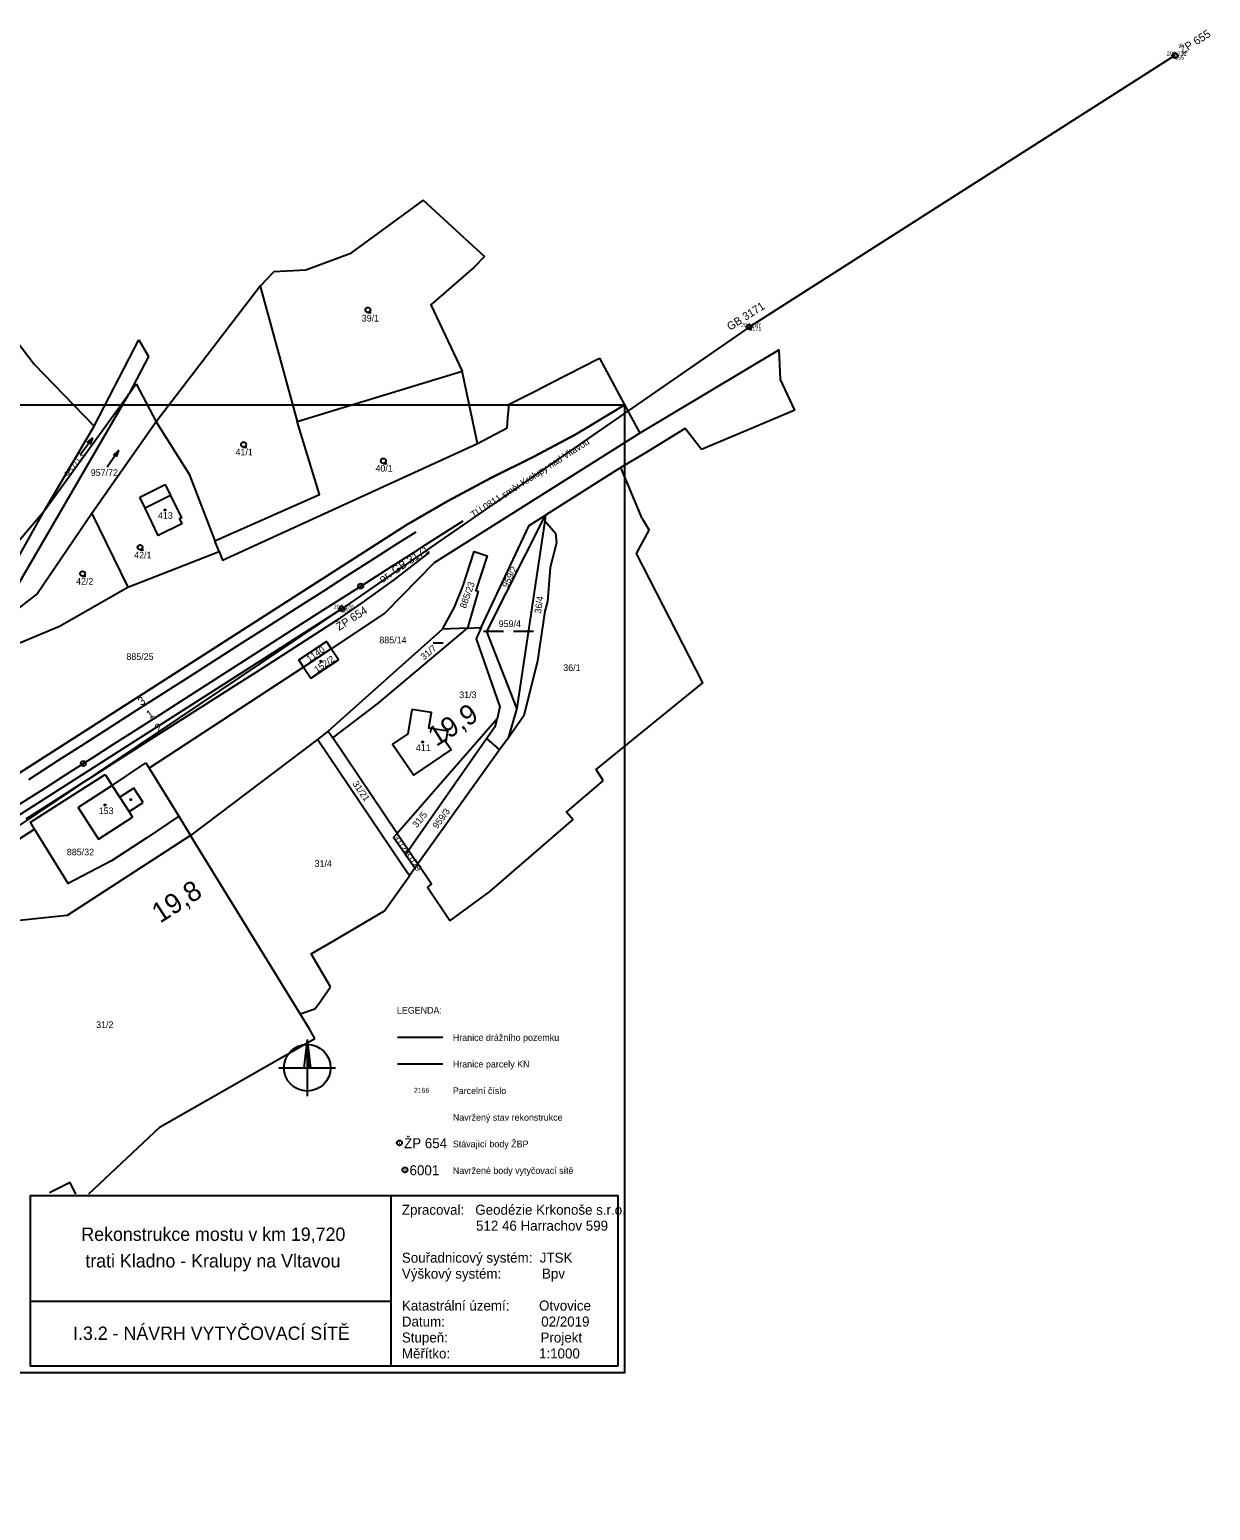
# Model space of a CAD drawing. Extents: x -752210 to -751291, y -1028374 to -1027785.
# Drawn here: x -751645.7 to -751290.6, y -1028230 to -1027784.8 of the extents above; entities that cross this region are included whole.
import ezdxf

# ---------------------------------------------------------------- set-up
doc = ezdxf.new("R2010")
doc.units = 0
for name, color, linetype in [('02_Osa_koleje', 7, 'Continuous'), ('03_Staničení', 7, 'Continuous'), ('Legenda', 7, 'Continuous'), ('Legenda 1', 7, 'Continuous'), ('Legenda 2', 7, 'Continuous'), ('Vrstva 4', 7, 'Continuous'), ('Vrstva 53', 7, 'Continuous'), ('Vrstva 55', 7, 'Continuous'), ('Vrstva 56', 7, 'Continuous'), ('Vrstva 57', 7, 'Continuous'), ('Vrstva 58', 7, 'Continuous'), ('Vrstva 59', 7, 'Continuous'), ('Vrstva 60', 7, 'Continuous'), ('Vrstva 61', 7, 'Continuous'), ('Vrstva 63', 7, 'Continuous')]:
    doc.layers.add(name, color=color, linetype=linetype)

msp = doc.modelspace()

# ---------------------------------------------------------------- linework, layer by layer
at = {"layer": '02_Osa_koleje'}
for p, q in [((-751535.5, -1027939.59), (-751529.38, -1027935.82)), ((-751541.77, -1027943.62), (-751535.5, -1027939.59)), ((-751536.85, -1027946.23), (-751529.25, -1027941.37)), ((-751527.97, -1027944.03), (-751525.45, -1027941.98)), ((-751550.25, -1027949.06), (-751541.77, -1027943.62)), ((-751544.45, -1027951.09), (-751536.85, -1027946.23)), ((-751536.02, -1027950.26), (-751527.97, -1027944.03)), ((-751557.18, -1027953.5), (-751550.25, -1027949.06)), ((-751551.57, -1027955.64), (-751544.45, -1027951.09)), ((-751545.62, -1027957.19), (-751536.02, -1027950.26)), ((-751565.35, -1027958.72), (-751557.18, -1027953.5)), ((-751557.44, -1027959.4), (-751551.57, -1027955.64)), ((-751573.24, -1027963.75), (-751565.35, -1027958.72)), ((-751565.26, -1027964.39), (-751557.44, -1027959.4)), ((-751552.14, -1027961.63), (-751545.62, -1027957.19)), ((-751581.95, -1027969.31), (-751573.24, -1027963.75)), ((-751569.81, -1027967.31), (-751565.26, -1027964.39)), ((-751560.92, -1027967.3), (-751552.14, -1027961.63)), ((-751588.99, -1027973.81), (-751581.95, -1027969.31)), ((-751576.84, -1027971.8), (-751569.81, -1027967.31)), ((-751569.42, -1027972.75), (-751560.92, -1027967.3)), ((-751584.69, -1027976.81), (-751576.84, -1027971.8)), ((-751577.55, -1027977.95), (-751569.42, -1027972.75)), ((-751597.35, -1027979.15), (-751588.99, -1027973.81)), ((-751592.46, -1027981.78), (-751584.69, -1027976.81)), ((-751585.46, -1027983), (-751577.55, -1027977.95)), ((-751605.88, -1027984.61), (-751597.35, -1027979.15)), ((-751599.97, -1027986.58), (-751592.46, -1027981.78)), ((-751614.37, -1027990.06), (-751605.88, -1027984.61)), ((-751606.23, -1027990.59), (-751599.97, -1027986.58)), ((-751593.8, -1027988.33), (-751585.46, -1027983)), ((-751622.32, -1027995.15), (-751614.37, -1027990.06)), ((-751613.64, -1027995.33), (-751606.23, -1027990.59)), ((-751601.83, -1027993.46), (-751593.8, -1027988.33)), ((-751630.17, -1028000.17), (-751622.32, -1027995.15)), ((-751621.23, -1028000.17), (-751613.64, -1027995.33)), ((-751608.88, -1027997.98), (-751601.83, -1027993.46)), ((-751636.92, -1028004.49), (-751630.17, -1028000.17)), ((-751626.18, -1028003.34), (-751621.23, -1028000.17)), ((-751616.69, -1028002.97), (-751608.88, -1027997.98)), ((-751645.91, -1028010.23), (-751636.92, -1028004.49)), ((-751633.49, -1028008.01), (-751626.18, -1028003.34)), ((-751624.19, -1028007.75), (-751616.69, -1028002.97)), ((-751640.92, -1028012.76), (-751633.49, -1028008.01)), ((-751630.51, -1028011.79), (-751624.19, -1028007.75)), ((-751648.69, -1028017.73), (-751640.92, -1028012.76)), ((-751638.2, -1028016.71), (-751630.51, -1028011.79)), ((-751646.64, -1028022.11), (-751638.2, -1028016.71))]:
    msp.add_line(p, q, dxfattribs=at)
msp.add_lwpolyline([(-751529.25, -1027941.37), (-751526.83, -1027939.82), (-751515.32, -1027932.45)], dxfattribs=at)
at = {"layer": '03_Staničení'}
for centre in [(-751546.08, -1027952.12), (-751629.49, -1028005.46)]:
    msp.add_circle(centre, 0.75, dxfattribs=at)
at = {"layer": 'Legenda 1'}
for p, q in [((-751562.16, -1028088.42), (-751563.17, -1028096.92)), ((-751562.16, -1028088.42), (-751562.16, -1028105.42)), ((-751562.16, -1028088.42), (-751561.16, -1028096.92)), ((-751562.16, -1028090.54), (-751561.41, -1028096.92)), ((-751562.16, -1028092.67), (-751561.66, -1028096.92)), ((-751570.66, -1028096.92), (-751553.66, -1028096.92)), ((-751562.16, -1028094.79), (-751561.91, -1028096.92)), ((-751562.16, -1028096.92), (-751562.16, -1028096.92)), ((-751536.92, -1028186.6), (-751536.92, -1028135.35)), ((-751536.92, -1028167.2), (-751645.4, -1028167.2))]:
    msp.add_line(p, q, dxfattribs=at)
msp.add_lwpolyline([(-751468.79, -1028186.6), (-751645.4, -1028186.6), (-751645.4, -1028135.35), (-751468.79, -1028135.35)], close=True, dxfattribs=at)
msp.add_circle((-751562.16, -1028096.92), 7, dxfattribs=at)
at = {"layer": 'Vrstva 4'}
msp.add_lwpolyline([(-751880.79, -1027897.6), (-751466.79, -1027897.6), (-751466.79, -1028188.6), (-751880.79, -1028188.6)], close=True, dxfattribs=at)
at = {"layer": 'Vrstva 53'}
msp.add_line((-751535.06, -1028087.71), (-751521.36, -1028087.71), dxfattribs=at)
for points in [[(-751890.97, -1028163.13), (-751806.75, -1028109.29), (-751808.53, -1028106.05), (-751798.29, -1028099.68), (-751750.57, -1028069.21), (-751709.61, -1028036.63), (-751702.85, -1028029.39), (-751690.7, -1028035.11), (-751634.83, -1027999.42), (-751532.07, -1027933.64), (-751519.82, -1027926.47), (-751506.87, -1027919.58), (-751494.13, -1027913.25), (-751481.54, -1027906.54), (-751469.19, -1027899.14), (-751466.79, -1027897.6)], [(-751462.19, -1027906.18), (-751523.97, -1027945.11), (-751538.82, -1027960.28), (-751554.98, -1027970.94), (-751563.33, -1027976.45), (-751609.72, -1028006.9), (-751600.73, -1028021.25), (-751610.42, -1028027.79), (-751621, -1028034.71), (-751634.07, -1028041.54), (-751644.14, -1028025.2), (-751657.66, -1028033.82)]]:
    msp.add_lwpolyline(points, dxfattribs=at)
at = {"layer": 'Vrstva 55'}
for p, q in [((-751514.9, -1027847.48), (-751527.35, -1027836.07)), ((-751514.9, -1027847.48), (-751508.89, -1027852.99)), ((-751670.74, -1027850.8), (-751644.31, -1027885.35)), ((-751572.26, -1027857.64), (-751576.37, -1027861.95)), ((-751576.37, -1027861.95), (-751607.59, -1027902.71)), ((-751576.37, -1027861.95), (-751565.18, -1027902.61)), ((-751626.22, -1027904.08), (-751612.77, -1027878.04)), ((-751612.77, -1027878.04), (-751609.94, -1027883.14)), ((-751609.94, -1027883.14), (-751615.69, -1027894.18)), ((-751489.04, -1027891.13), (-751474.31, -1027883.58)), ((-751474.31, -1027883.58), (-751466.79, -1027897.6)), ((-751420.23, -1027881.1), (-751462.19, -1027906.18)), ((-751419.83, -1027889.96), (-751420.23, -1027881.1)), ((-751626.22, -1027904.08), (-751644.31, -1027885.35)), ((-751565.18, -1027902.61), (-751515.53, -1027887.47)), ((-751511.01, -1027909.22), (-751515.53, -1027887.47)), ((-751615.69, -1027894.18), (-751613.65, -1027891.36)), ((-751613.65, -1027891.36), (-751607.59, -1027902.71)), ((-751493.66, -1027893.5), (-751489.04, -1027891.13)), ((-751415.54, -1027899.18), (-751419.83, -1027889.96)), ((-751656.71, -1027964.65), (-751615.69, -1027894.18)), ((-751641.14, -1027929.37), (-751615.69, -1027894.18)), ((-751466.79, -1027897.6), (-751469.19, -1027899.14)), ((-751466.79, -1027897.6), (-751462.19, -1027906.18)), ((-751641.14, -1027929.37), (-751626.22, -1027904.08)), ((-751607.59, -1027902.71), (-751626.99, -1027930.26)), ((-751460.76, -1027912.3), (-751467.89, -1027916.43)), ((-751467.89, -1027916.43), (-751490.52, -1027930.81)), ((-751461.44, -1027931.84), (-751467.89, -1027916.43)), ((-751612.52, -1027925.39), (-751604.88, -1027921.62)), ((-751626.99, -1027930.26), (-751616.15, -1027952.42)), ((-751490.76, -1027932.54), (-751499.13, -1027988.78)), ((-751490.52, -1027930.81), (-751490.76, -1027932.54)), ((-751461.44, -1027931.84), (-751459.38, -1027935.34)), ((-751616.15, -1027952.42), (-751588.69, -1027941.76)), ((-751588.69, -1027941.76), (-751589.95, -1027938.49)), ((-751510.79, -1027953.68), (-751513.96, -1027964.72)), ((-751521.54, -1027965.05), (-751517.93, -1027958.42)), ((-751513.96, -1027964.72), (-751521.54, -1027965.05)), ((-751513.96, -1027964.72), (-751509.88, -1027964.53)), ((-751521.54, -1027965.05), (-751555.86, -1027995.74)), ((-751554.98, -1027970.94), (-751563.33, -1027976.45)), ((-751563.33, -1027976.45), (-751609.72, -1028006.9)), ((-751499.13, -1027988.78), (-751501.78, -1027997.8)), ((-751555.86, -1027995.74), (-751559.11, -1027998.2)), ((-751555.86, -1027995.74), (-751554.45, -1027997.78)), ((-751505.06, -1027992), (-751535.11, -1028026.46)), ((-751559.11, -1027998.2), (-751597.31, -1028027.06)), ((-751535.11, -1028026.46), (-751554.45, -1027997.78)), ((-751531.7, -1028031.5), (-751508.24, -1027997.97)), ((-751508.24, -1027997.97), (-751504.35, -1028001.39)), ((-751501.78, -1027997.8), (-751504.35, -1028001.39)), ((-751504.35, -1028001.39), (-751528.9, -1028035.64)), ((-751610.74, -1028005.23), (-751609.72, -1028006.9)), ((-751609.72, -1028006.9), (-751600.73, -1028021.25)), ((-751600.73, -1028021.25), (-751597.31, -1028027.06)), ((-751564.25, -1028080.75), (-751597.31, -1028027.06)), ((-751535.11, -1028026.46), (-751531.7, -1028031.5)), ((-751531.7, -1028031.5), (-751532.76, -1028032.72)), ((-751531.7, -1028031.5), (-751528.9, -1028035.64)), ((-751529.84, -1028036.97), (-751532.76, -1028032.72)), ((-751528.9, -1028035.64), (-751529.84, -1028036.97)), ((-751538.93, -1028049.78), (-751531.43, -1028039.2)), ((-751529.84, -1028036.97), (-751531.43, -1028039.2)), ((-751519.27, -1028052.78), (-751525.97, -1028042.75)), ((-751558.81, -1028077.79), (-751555.13, -1028072.6)), ((-751561.61, -1028085.17), (-751564.25, -1028080.75)), ((-751577.95, -1028098.41), (-751559.85, -1028088.11)), ((-751559.85, -1028088.11), (-751561.61, -1028085.17)), ((-751535.06, -1028095.71), (-751521.36, -1028095.71))]:
    msp.add_line(p, q, dxfattribs=at)
for points in [[(-751527.35, -1027836.07), (-751549.35, -1027852.19), (-751562.57, -1027857.16), (-751572.26, -1027857.64)], [(-751508.89, -1027852.99), (-751512.04, -1027856.33), (-751525.01, -1027867.6), (-751515.53, -1027887.47)], [(-751511.01, -1027909.22), (-751502.05, -1027904.53), (-751501.8, -1027901.52), (-751501.41, -1027897.47), (-751493.66, -1027893.5)], [(-751469.19, -1027899.14), (-751481.54, -1027906.54), (-751494.13, -1027913.25), (-751506.87, -1027919.58), (-751519.82, -1027926.47), (-751532.07, -1027933.64), (-751634.83, -1027999.42), (-751690.7, -1028035.11), (-751702.85, -1028029.39)], [(-751415.54, -1027899.18), (-751429.76, -1027905.22), (-751434.82, -1027907.37), (-751443.56, -1027911.08)], [(-751607.59, -1027902.71), (-751597.69, -1027918.48), (-751589.95, -1027938.49)], [(-751589.95, -1027938.49), (-751558.45, -1027924.61), (-751565.18, -1027902.61)], [(-751462.19, -1027906.18), (-751523.97, -1027945.11), (-751538.82, -1027960.28), (-751554.98, -1027970.94)], [(-751443.56, -1027911.08), (-751448.52, -1027904.72), (-751460.76, -1027912.3)], [(-751588.69, -1027941.76), (-751587.61, -1027944.36), (-751511.01, -1027909.22)], [(-751604.88, -1027921.62), (-751603.25, -1027924.91), (-751599.95, -1027931.6), (-751600.61, -1027931.93), (-751599.87, -1027933.41), (-751606.96, -1027936.93), (-751610.94, -1027928.67), (-751612.52, -1027925.39)], [(-751672, -1027960.17), (-751661.99, -1027953.87), (-751641.14, -1027929.37)], [(-751668.79, -1027968.97), (-751658.03, -1027959.34), (-751641.14, -1027929.37)], [(-751626.99, -1027930.26), (-751643.3, -1027954.3), (-751656.71, -1027964.65)], [(-751509.88, -1027964.53), (-751495.38, -1027933.9), (-751490.52, -1027930.81)], [(-751499.13, -1027988.78), (-751508.14, -1027965.79), (-751490.52, -1027930.81)], [(-751490.76, -1027932.54), (-751487.53, -1027936.17), (-751487.21, -1027939.13), (-751489.07, -1027946.51), (-751489.95, -1027956.74), (-751490.69, -1027959.66), (-751492.95, -1027974.6), (-751497.03, -1027991.17), (-751501.78, -1027997.8)], [(-751473.18, -1028010.52), (-751475.29, -1028007.29), (-751443.25, -1027981.25), (-751463.14, -1027942.28), (-751459.38, -1027935.34)], [(-751517.93, -1027958.42), (-751515.42, -1027952.2), (-751511.94, -1027941.75), (-751508.1, -1027943), (-751511.47, -1027953.46), (-751510.79, -1027953.68)], [(-751651.99, -1027970.58), (-751636.62, -1027964.12), (-751616.15, -1027952.42)], [(-751554.45, -1027997.78), (-751541.05, -1027987.48), (-751513.96, -1027964.72)], [(-751509.88, -1027964.53), (-751511.41, -1027967.96), (-751504.21, -1027988.42), (-751505.06, -1027992)], [(-751563.33, -1027976.45), (-751564.74, -1027974.3), (-751556.39, -1027968.8), (-751554.98, -1027970.94)], [(-751563.33, -1027976.45), (-751561.13, -1027979.79), (-751552.78, -1027974.28), (-751554.98, -1027970.94)], [(-751530.72, -1027989.19), (-751531.91, -1027996.52), (-751536.51, -1027999.67), (-751530.08, -1028008.97), (-751518.89, -1028001.3), (-751520.44, -1027999.07), (-751519.9, -1027995.71), (-751525.59, -1027994.81), (-751524.75, -1027990.16), (-751530.72, -1027989.19)], [(-751508.24, -1027997.97), (-751505.57, -1027994.16), (-751505.06, -1027992)], [(-751531.43, -1028039.2), (-751533.79, -1028035.7), (-751559.11, -1027998.2)], [(-751644.14, -1028025.2), (-751645.38, -1028023.11), (-751622.97, -1028008.73)], [(-751622.97, -1028008.73), (-751620.78, -1028012.09), (-751610.74, -1028005.23)], [(-751611.54, -1028017.13), (-751614.28, -1028012.89), (-751618.5, -1028015.62), (-751620.78, -1028012.09), (-751631.03, -1028018.71), (-751624.93, -1028028.16), (-751614.68, -1028021.54), (-751615.76, -1028019.86), (-751611.54, -1028017.13)], [(-751473.18, -1028010.52), (-751484.17, -1028020.02), (-751482.24, -1028022.26)], [(-751600.73, -1028021.25), (-751610.42, -1028027.79), (-751621, -1028034.71), (-751634.07, -1028041.54), (-751644.14, -1028025.2)], [(-751519.27, -1028052.78), (-751507.37, -1028043.99), (-751482.24, -1028022.26)], [(-751811.98, -1028131.93), (-751700.39, -1028060.59), (-751700.15, -1028061), (-751685.1, -1028051.35), (-751685.36, -1028050.92), (-751657.93, -1028033.4), (-751657.66, -1028033.82), (-751644.14, -1028025.2)], [(-751597.31, -1028027.06), (-751634.36, -1028051.12), (-751685.04, -1028056.42), (-751698.4, -1028064.61)], [(-751532.76, -1028032.72), (-751536.2, -1028027.71), (-751535.11, -1028026.46)], [(-751525.97, -1028042.75), (-751524.75, -1028041.78), (-751528.9, -1028035.64)], [(-751555.13, -1028072.6), (-751560.94, -1028062.65), (-751554.11, -1028058.66), (-751538.93, -1028049.78)], [(-751564.25, -1028080.75), (-751559.85, -1028079.26), (-751558.81, -1028077.79)], [(-751627.84, -1028134.79), (-751606.35, -1028114.7), (-751577.95, -1028098.41)], [(-751631.71, -1028134.9), (-751633.5, -1028131.42), (-751639.67, -1028134.57)]]:
    msp.add_lwpolyline(points, dxfattribs=at)
at = {"layer": 'Vrstva 56'}
for p, q in [((-751603.25, -1027924.91), (-751610.94, -1027928.67)), ((-751615.76, -1028019.86), (-751618.5, -1028015.62))]:
    msp.add_line(p, q, dxfattribs=at)
at = {"layer": 'Vrstva 58'}
for p, q in [((-751543.94, -1027869.85), (-751542.94, -1027869.85)), ((-751630.38, -1027912.48), (-751626.78, -1027907.68)), ((-751622.31, -1027916.3), (-751618.89, -1027911.37)), ((-751581.3, -1027910.33), (-751580.3, -1027910.33)), ((-751539.26, -1027915.25), (-751538.26, -1027915.25)), ((-751612.42, -1027941.21), (-751611.42, -1027941.21)), ((-751629.72, -1027949.14), (-751628.72, -1027949.14)), ((-751524.26, -1027969.13), (-751521.26, -1027969.13)), ((-751509.14, -1027965.72), (-751503.14, -1027965.72)), ((-751500.14, -1027965.72), (-751494.14, -1027965.72))]:
    msp.add_line(p, q, dxfattribs=at)
for points in [[(-751628.38, -1027908.98), (-751626.78, -1027907.68), (-751627.58, -1027909.58)], [(-751620.44, -1027912.73), (-751618.89, -1027911.37), (-751619.62, -1027913.3)]]:
    msp.add_lwpolyline(points, dxfattribs=at)
for centre in [(-751543.94, -1027869.1), (-751581.3, -1027909.58), (-751539.26, -1027914.5), (-751612.42, -1027940.46), (-751629.72, -1027948.39)]:
    msp.add_circle(centre, 0.75, dxfattribs=at)
at = {"layer": 'Vrstva 59'}
for centre in [(-751604.94, -1027929.24), (-751558.09, -1027974.76), (-751527.47, -1027999), (-751622.96, -1028017.93), (-751615.24, -1028016.34)]:
    msp.add_circle(centre, 0.175, dxfattribs=at)
at = {"layer": 'Vrstva 60'}
for p, q in [((-751301.25, -1027792.61), (-751301.25, -1027792.61)), ((-751429.27, -1027874.23), (-751429.27, -1027874.23)), ((-751551.77, -1027958.95), (-751551.77, -1027958.95))]:
    msp.add_line(p, q, dxfattribs=at)
at = {"layer": 'Vrstva 63'}
for p, q in [((-751301.25, -1027792.61), (-751429.27, -1027874.23)), ((-751301.29, -1027792.64), (-751301.2, -1027792.59)), ((-751429.27, -1027874.23), (-751551.77, -1027958.95)), ((-751429.31, -1027874.26), (-751429.23, -1027874.21)), ((-751551.77, -1027958.95), (-751975.84, -1028230)), ((-751715.69, -1028069.13), (-751551.77, -1027958.95)), ((-751551.81, -1027958.97), (-751551.73, -1027958.92)), ((-751534.48, -1028119.51), (-751534.38, -1028119.51)), ((-751532.83, -1028127.63), (-751532.73, -1028127.63))]:
    msp.add_line(p, q, dxfattribs=at)
for centre in [(-751301.25, -1027792.61), (-751429.27, -1027874.23), (-751551.77, -1027958.95), (-751534.43, -1028119.51), (-751532.78, -1028127.63)]:
    msp.add_circle(centre, 0.756, dxfattribs=at)

# ---------------------------------------------------------------- texts
at = {"layer": '02_Osa_koleje'}
for s, height, rotation, p in [('TÚ 0811 směr Kralupy nad Vltavou', 2, 32.6028, (-751512.17, -1027931.68)), ('3', 2.5, 32.6084, (-751612.12, -1027988.22)), ('1', 2.5, 32.6084, (-751609.6, -1027992.17)), ('2', 2.5, 32.6084, (-751607, -1027996.23))]:
    msp.add_text(s, height=height, rotation=rotation, dxfattribs=at).set_placement(p)
at = {"layer": '03_Staničení'}
for s, rotation, p in [('19,9', 32.5948, (-751523.37, -1028000.52)), ('19,8', 32.5903, (-751606.44, -1028053.63))]:
    msp.add_text(s, height=6, rotation=rotation, dxfattribs=at).set_placement(p)
at = {"layer": 'Legenda'}
msp.add_text('LEGENDA:', height=2, rotation=360, dxfattribs=at).set_placement((-751535.2, -1028080.64))
at = {"layer": 'Legenda 1'}
for s, height, p in [('Zpracoval:   Geodézie Krkonoše s.r.o.', 3, (-751533.7, -1028141.12)), ('                    512 46 Harrachov 599', 3, (-751533.7, -1028145.92)), ('Rekonstrukce mostu v km 19,720', 4, (-751630.09, -1028148.96)), ('trati Kladno - Kralupy na Vltavou', 4, (-751628.89, -1028156.96)), ('Souřadnicový systém:  JTSK', 3, (-751533.7, -1028155.52)), ('Výškový systém:           Bpv', 3, (-751533.7, -1028160.32)), ('Katastrální území:        Otvovice', 3, (-751533.7, -1028169.92)), ('I.3.2 - NÁVRH VYTYČOVACÍ SÍTĚ', 4, (-751632.57, -1028178.73)), ('Datum:                          02/2019', 3, (-751533.7, -1028174.72)), ('Stupeň:                         Projekt', 3, (-751533.7, -1028179.52)), ('Měřítko:                        1:1000', 3, (-751533.7, -1028184.32))]:
    msp.add_text(s, height=height, dxfattribs=at).set_placement(p)
at = {"layer": 'Legenda 2'}
for s, p in [('Hranice drážního pozemku', (-751518.38, -1028088.84)), ('Hranice parcely KN', (-751518.38, -1028096.84)), ('Parcelní číslo', (-751518.38, -1028104.84)), ('Navržený stav rekonstrukce', (-751518.38, -1028112.84)), ('Stávající body ŽBP', (-751518.38, -1028120.84)), ('Navržené body vytyčovací sítě', (-751518.38, -1028128.84))]:
    msp.add_text(s, height=2, rotation=360, dxfattribs=at).set_placement(p)
at = {"layer": 'Vrstva 57'}
for s, p in [('39/1', (-751545.77, -1027872.58)), ('41/1', (-751583.73, -1027912.82)), ('40/1', (-751541.66, -1027917.71)), ('957/72', (-751627.27, -1027918.99)), ('413', (-751607.06, -1027931.88)), ('42/1', (-751614.22, -1027943.8)), ('42/2', (-751631.68, -1027951.68)), ('959/4', (-751504.59, -1027964.44)), ('885/14', (-751540.48, -1027969.33)), ('885/25', (-751616.55, -1027974.32)), ('36/1', (-751485.18, -1027977.65)), ('31/3', (-751516.45, -1027985.8)), ('411', (-751529.5, -1028001.7)), ('153', (-751624.87, -1028020.68)), ('885/32', (-751634.45, -1028033.06)), ('31/4', (-751559.96, -1028036.52)), ('31/2', (-751625.65, -1028084.98))]:
    msp.add_text(s, height=2, dxfattribs=at).set_placement(p)
for s, height, rotation, p in [('957/13', 2, 55, (-751633.78, -1027919.63)), ('959/2', 2, 63, (-751501.94, -1027952.82)), ('885/23', 2, 70, (-751514.54, -1027958.96)), ('36/4', 2, 82, (-751491.85, -1027960.48)), ('1140', 2, 35, (-751561.53, -1027975.07)), ('152/2', 2, 34, (-751559.27, -1027978.29)), ('31/7', 2, 40, (-751527.07, -1027974.47)), ('31/21', 2, 305, (-751548.68, -1028011.57)), ('31/5', 2, 51, (-751529.18, -1028024.94)), ('959/3', 2, 54, (-751523.04, -1028025.25)), ('31/28', 2, 305, (-751536.47, -1028027.74)), ('31/29', 2, 307, (-751533.12, -1028032.74)), ('2166', 1.5, 360, (-751530.08, -1028104.46))]:
    msp.add_text(s, height=height, rotation=rotation, dxfattribs=at).set_placement(p)
at = {"layer": 'Vrstva 60'}
for s, p in [('655', (-751301.25, -1027793.81)), ('3171', (-751429.27, -1027875.43)), ('654', (-751551.77, -1027960.15))]:
    msp.add_text(s, height=1.2, dxfattribs=at).set_placement(p)
at = {"layer": 'Vrstva 61'}
for s, p in [('203.732', (-751303.69, -1027792.61)), ('204.287', (-751431.72, -1027874.23)), ('205.070', (-751554.22, -1027958.95))]:
    msp.add_text(s, height=1.2, dxfattribs=at).set_placement(p)
at = {"layer": 'Vrstva 63'}
for s, height, rotation, p in [('ŽP 655', 2.4, 32.593, (-751298.96, -1027792.28)), ('GB 3171', 2.4, 32.595, (-751435.01, -1027875.39)), ('or. GB 3171', 2.4, 33.8047, (-751539.62, -1027951.3)), ('ŽP 654', 2.4, 32.593, (-751552.57, -1027965.62)), ('ŽP 654', 3, 360, (-751533.05, -1028121.11)), ('6001', 3, 360, (-751531.39, -1028129.24))]:
    msp.add_text(s, height=height, rotation=rotation, dxfattribs=at).set_placement(p)

doc.saveas('drawing.dxf')
